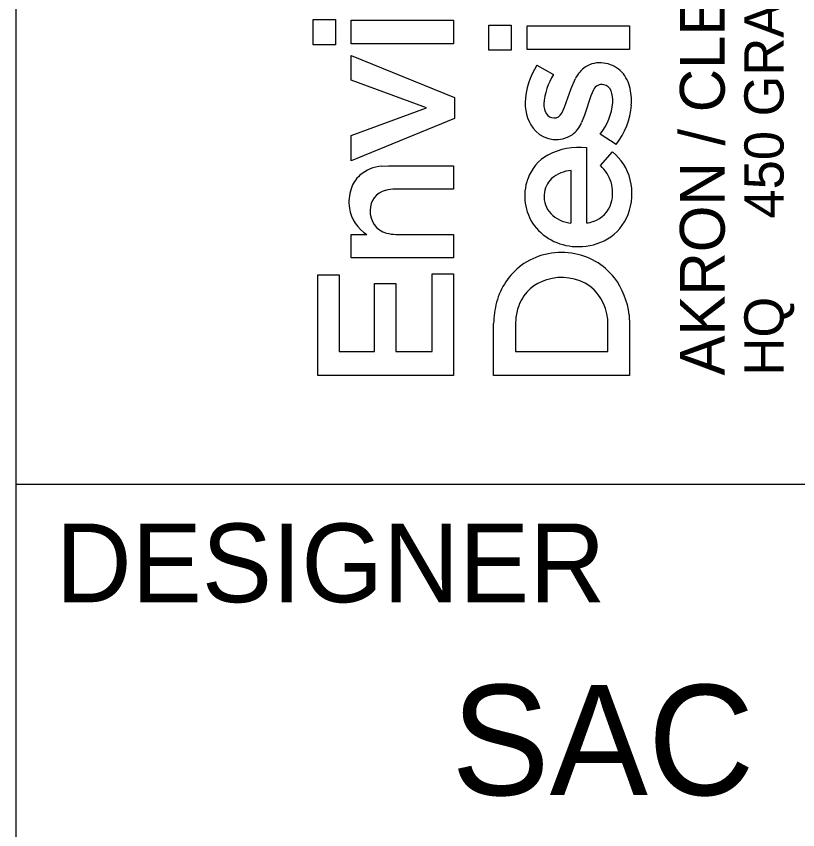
# Model space of a CAD drawing. Extents: x -0.3 to 34, y 0 to 22.
# Drawn here: x 32 to 32.993, y 2.061 to 3.094 of the extents above; entities that cross this region are included whole.
import ezdxf

# ---------------------------------------------------------------- set-up
doc = ezdxf.new("R2010")
doc.units = 0
doc.layers.add('SH_Border', color=7, linetype='Continuous')
doc.layers.add('SH_Data', color=7, linetype='Continuous')

msp = doc.modelspace()

# ---------------------------------------------------------------- linework, layer by layer
at = {"layer": 'SH_Border'}
for p, q in [((32, 0.5), (32, 21.5)), ((32, 2.5), (33.5, 2.5))]:
    msp.add_line(p, q, dxfattribs=at)
at = {"layer": 'SH_Data'}
for p, q in [((32.3771, 3.0582), (32.3771, 3.0903)), ((32.3771, 3.0903), (32.4054, 3.0903)), ((32.4054, 3.0903), (32.4054, 3.0582)), ((32.4254, 3.0594), (32.4254, 3.0893)), ((32.4254, 3.0893), (32.5557, 3.0893)), ((32.5557, 3.0893), (32.5557, 3.0594)), ((32.6005, 3.0511), (32.6005, 3.0832)), ((32.6005, 3.0832), (32.6289, 3.0832)), ((32.6289, 3.0832), (32.6289, 3.0511)), ((32.6489, 3.0523), (32.6489, 3.0822)), ((32.6489, 3.0822), (32.7792, 3.0822)), ((32.7792, 3.0822), (32.7792, 3.0523)), ((32.5557, 3.0594), (32.4254, 3.0594)), ((32.4054, 3.0582), (32.3771, 3.0582)), ((32.6289, 3.0511), (32.6005, 3.0511)), ((32.7792, 3.0523), (32.6489, 3.0523)), ((32.4254, 3.0133), (32.4254, 3.0446)), ((32.4254, 3.0446), (32.5567, 2.9913)), ((32.6615, 3.0321), (32.6827, 3.0203)), ((32.5212, 2.978), (32.4254, 3.0133)), ((32.7048, 3.0026), (32.7104, 3.0153)), ((32.6967, 2.9787), (32.7048, 3.0026)), ((32.7334, 3.001), (32.7298, 2.9933)), ((32.5567, 2.9913), (32.5567, 2.9644)), ((32.7298, 2.9933), (32.7221, 2.9688)), ((32.4254, 2.9429), (32.5212, 2.978)), ((32.693, 2.9712), (32.6967, 2.9787)), ((32.7221, 2.9688), (32.7182, 2.9592)), ((32.5567, 2.9644), (32.4254, 2.9109)), ((32.4254, 2.9109), (32.4254, 2.9429)), ((32.7621, 2.9314), (32.742, 2.9447)), ((32.7245, 2.9275), (32.7246, 2.8319)), ((32.7423, 2.9046), (32.7577, 2.922)), ((32.4644, 2.904), (32.4729, 2.9044)), ((32.4729, 2.9044), (32.5557, 2.9044)), ((32.5557, 2.9044), (32.5557, 2.8746)), ((32.7049, 2.8318), (32.7049, 2.8983)), ((32.5557, 2.8746), (32.4814, 2.8746)), ((32.7036, 2.8317), (32.7049, 2.8318)), ((32.4254, 2.7875), (32.4254, 2.8173)), ((32.4254, 2.8173), (32.4455, 2.8173)), ((32.4822, 2.8173), (32.5557, 2.8173)), ((32.5557, 2.8173), (32.5557, 2.7876)), ((32.5557, 2.7876), (32.4254, 2.7875)), ((32.383, 2.6379), (32.383, 2.766)), ((32.383, 2.766), (32.4101, 2.766)), ((32.4101, 2.766), (32.4101, 2.6683)), ((32.5286, 2.6683), (32.5286, 2.7672)), ((32.5286, 2.7672), (32.5557, 2.7672)), ((32.5557, 2.7672), (32.5557, 2.6379)), ((32.455, 2.6683), (32.455, 2.7549)), ((32.455, 2.7549), (32.4822, 2.7549)), ((32.4822, 2.7549), (32.4822, 2.6683)), ((32.6347, 2.7118), (32.6341, 2.7023)), ((32.7785, 2.715), (32.7792, 2.7021)), ((32.6064, 2.638), (32.6064, 2.704)), ((32.6341, 2.7023), (32.6341, 2.6684)), ((32.7515, 2.6683), (32.7515, 2.7024)), ((32.7792, 2.7021), (32.7792, 2.638)), ((32.4101, 2.6683), (32.455, 2.6683)), ((32.4822, 2.6683), (32.5286, 2.6683)), ((32.6341, 2.6684), (32.7515, 2.6683)), ((32.5557, 2.6379), (32.383, 2.6379)), ((32.7792, 2.638), (32.6064, 2.638))]:
    msp.add_line(p, q, dxfattribs=at)
for points in [[(32.3771, 3.0582), (32.3771, 3.0903), (32.4054, 3.0903), (32.4054, 3.0582)], [(32.4254, 3.0594), (32.4254, 3.0893), (32.5557, 3.0893), (32.5557, 3.0594)], [(32.6005, 3.0511), (32.6005, 3.0832), (32.6289, 3.0832), (32.6289, 3.0511)], [(32.6489, 3.0523), (32.6489, 3.0822), (32.7792, 3.0822), (32.7792, 3.0523)], [(32.4254, 2.9109), (32.4254, 2.9429), (32.5212, 2.978), (32.4254, 3.0133), (32.4254, 3.0446), (32.5567, 2.9913), (32.5567, 2.9644)], [(32.383, 2.6379), (32.383, 2.766), (32.4101, 2.766), (32.4101, 2.6683), (32.455, 2.6683), (32.455, 2.7549), (32.4822, 2.7549), (32.4822, 2.6683), (32.5286, 2.6683), (32.5286, 2.7672), (32.5557, 2.7672), (32.5557, 2.6379)]]:
    msp.add_lwpolyline(points, close=True, dxfattribs=at)
for points in [[(32.6615, 3.0321), (32.6827, 3.0203)], [(32.693, 2.9712), (32.6967, 2.9787), (32.7048, 3.0026), (32.7104, 3.0153)], [(32.7334, 3.001), (32.7298, 2.9933), (32.7221, 2.9688), (32.7182, 2.9592)], [(32.7621, 2.9314), (32.742, 2.9447)], [(32.7245, 2.9275), (32.7246, 2.8319)], [(32.7423, 2.9046), (32.7577, 2.922)], [(32.4644, 2.904), (32.4729, 2.9044), (32.5557, 2.9044), (32.5557, 2.8746), (32.4814, 2.8746)], [(32.7036, 2.8317), (32.7049, 2.8318), (32.7049, 2.8983)], [(32.4254, 2.7875), (32.4254, 2.8173), (32.4455, 2.8173)], [(32.4822, 2.8173), (32.5557, 2.8173), (32.5557, 2.7876), (32.4254, 2.7875)], [(32.7785, 2.715), (32.7792, 2.7021), (32.7792, 2.638), (32.6064, 2.638)], [(32.6347, 2.7118), (32.6341, 2.7023), (32.6341, 2.6684), (32.7515, 2.6683), (32.7515, 2.7024)], [(32.6064, 2.638), (32.6064, 2.704)]]:
    msp.add_lwpolyline(points, dxfattribs=at)
for centre, radius, start, end in [((32.7364, 2.9826), 0.0897, 146.531, 178.7571), ((32.7364, 2.9826), 0.0897, 146.531, 178.7571), ((32.7466, 2.9971), 0.0405, 125.5118, 153.4159), ((32.7466, 2.9971), 0.0405, 125.5118, 153.4159), ((32.7406, 3.0026), 0.0326, 80.1719, 122.5197), ((32.7406, 3.0026), 0.0326, 80.1719, 122.5197), ((32.7428, 2.9982), 0.0367, 47.7934, 84.6892), ((32.7428, 2.9982), 0.0367, 47.7934, 84.6892), ((32.7452, 2.9789), 0.0749, 146.5112, 176.9101), ((32.7452, 2.9789), 0.0749, 146.5112, 176.9101), ((32.7379, 2.9946), 0.0427, 14.9966, 46.2063), ((32.7379, 2.9946), 0.0427, 14.9966, 46.2063), ((32.7438, 2.9963), 0.0114, 76.6609, 155.7053), ((32.7438, 2.9963), 0.0114, 76.6609, 155.7053), ((32.744, 2.9951), 0.0126, 21.5098, 78.5262), ((32.744, 2.9951), 0.0126, 21.5098, 78.5262), ((32.7259, 2.9877), 0.0321, 354.5726, 22.068), ((32.7259, 2.9877), 0.0321, 354.5726, 22.068), ((32.7104, 2.9867), 0.0712, 355.8306, 15.3914), ((32.7104, 2.9867), 0.0712, 355.8306, 15.3914), ((32.6967, 2.9824), 0.0501, 177.5366, 222.7932), ((32.6967, 2.9824), 0.0501, 177.5366, 222.7932), ((32.6931, 2.9823), 0.0228, 178.4747, 211.0868), ((32.6931, 2.9823), 0.0228, 178.4747, 211.0868), ((32.6825, 2.9915), 0.0757, 321.811, 354.7969), ((32.6825, 2.9915), 0.0757, 321.811, 354.7969), ((32.6895, 2.9882), 0.0922, 321.9777, 355.8738), ((32.6895, 2.9882), 0.0922, 321.9777, 355.8738), ((32.6833, 2.9767), 0.0115, 212.2368, 268.3777), ((32.6833, 2.9767), 0.0115, 212.2368, 268.3777), ((32.6834, 2.9759), 0.0107, 267.716, 333.7337), ((32.6834, 2.9759), 0.0107, 267.716, 333.7337), ((32.681, 2.9758), 0.0408, 308.0877, 335.9874), ((32.681, 2.9758), 0.0408, 308.0877, 335.9874), ((32.686, 2.9753), 0.0375, 225.9854, 302.4797), ((32.686, 2.9753), 0.0375, 225.9854, 302.4797), ((32.7152, 2.8441), 0.0838, 83.615, 118.2876), ((32.7152, 2.8441), 0.0838, 83.615, 118.2876), ((32.7024, 2.8691), 0.0558, 118.8308, 160.6244), ((32.7024, 2.8691), 0.0558, 118.8308, 160.6244), ((32.7174, 2.8717), 0.0644, 13.5336, 51.3615), ((32.7174, 2.8717), 0.0644, 13.5336, 51.3615), ((32.4687, 2.8543), 0.0499, 94.9696, 130.2225), ((32.4687, 2.8543), 0.0499, 94.9696, 130.2225), ((32.7038, 2.8656), 0.0549, 19.0357, 45.4406), ((32.7038, 2.8656), 0.0549, 19.0357, 45.4406), ((32.7079, 2.8561), 0.0424, 94.008, 130.8817), ((32.7079, 2.8561), 0.0424, 94.008, 130.8817), ((32.4635, 2.8626), 0.0402, 132.2219, 161.6818), ((32.4635, 2.8626), 0.0402, 132.2219, 161.6818), ((32.7104, 2.8661), 0.0644, 160.5201, 215.7831), ((32.7104, 2.8661), 0.0644, 160.5201, 215.7831), ((32.7005, 2.8663), 0.0298, 132.9851, 177.179), ((32.7005, 2.8663), 0.0298, 132.9851, 177.179), ((32.7107, 2.8697), 0.047, 344.6059, 17.007), ((32.7107, 2.8697), 0.047, 344.6059, 17.007), ((32.7064, 2.8692), 0.0758, 339.3542, 13.3785), ((32.7064, 2.8692), 0.0758, 339.3542, 13.3785), ((32.4787, 2.8582), 0.056, 162.2736, 187.7919), ((32.4787, 2.8582), 0.056, 162.2736, 187.7919), ((32.4748, 2.8487), 0.025, 103.6865, 182.2187), ((32.4748, 2.8487), 0.025, 103.6865, 182.2187), ((32.4811, 2.8286), 0.046, 89.6049, 105.3284), ((32.4811, 2.8286), 0.046, 89.6049, 105.3284), ((32.7017, 2.865), 0.0311, 175.0013, 223.283), ((32.7017, 2.865), 0.0311, 175.0013, 223.283), ((32.7224, 2.8671), 0.035, 288.0077, 343.5508), ((32.7224, 2.8671), 0.035, 288.0077, 343.5508), ((32.4703, 2.858), 0.0476, 188.962, 238.7037), ((32.4703, 2.858), 0.0476, 188.962, 238.7037), ((32.4773, 2.8456), 0.0276, 175.5854, 255.1439), ((32.4773, 2.8456), 0.0276, 175.5854, 255.1439), ((32.7089, 2.8736), 0.0423, 225.0619, 262.7974), ((32.7089, 2.8736), 0.0423, 225.0619, 262.7974), ((32.7189, 2.8652), 0.0626, 300.9427, 338.7323), ((32.7189, 2.8652), 0.0626, 300.9427, 338.7323), ((32.7247, 2.8522), 0.0202, 269.7003, 294.8711), ((32.7247, 2.8522), 0.0202, 269.7003, 294.8711), ((32.7125, 2.8705), 0.0687, 217.7452, 271.6543), ((32.7125, 2.8705), 0.0687, 217.7452, 271.6543), ((32.4818, 2.8595), 0.0422, 254.0916, 270.5284), ((32.4818, 2.8595), 0.0422, 254.0916, 270.5284), ((32.7155, 2.8724), 0.0706, 269.2048, 300.3341), ((32.7155, 2.8724), 0.0706, 269.2048, 300.3341), ((32.6923, 2.7079), 0.0864, 81.194, 125.9984), ((32.6923, 2.7079), 0.0864, 81.194, 125.9984), ((32.6946, 2.7113), 0.0827, 37.8521, 82.402), ((32.6946, 2.7113), 0.0827, 37.8521, 82.402), ((32.6939, 2.7089), 0.0865, 127.2362, 165.148), ((32.6939, 2.7089), 0.0865, 127.2362, 165.148), ((32.6889, 2.7078), 0.054, 106.1881, 157.3861), ((32.6889, 2.7078), 0.054, 106.1881, 157.3861), ((32.6928, 2.6986), 0.0639, 55.6727, 107.2093), ((32.6928, 2.6986), 0.0639, 55.6727, 107.2093), ((32.6859, 2.7057), 0.0931, 5.7333, 37.304), ((32.6859, 2.7057), 0.0931, 5.7333, 37.304), ((32.6929, 2.705), 0.0587, 357.4662, 52.2665), ((32.6929, 2.705), 0.0587, 357.4662, 52.2665), ((32.7143, 2.7028), 0.1078, 164.7861, 179.3704), ((32.7143, 2.7028), 0.1078, 164.7861, 179.3704), ((32.6983, 2.7039), 0.0641, 157.3571, 172.9275), ((32.6983, 2.7039), 0.0641, 157.3571, 172.9275)]:
    msp.add_arc(centre, radius, start, end, dxfattribs=at)

# ---------------------------------------------------------------- texts
for s, height, p in [('450 GRANT ST., AKRON, OH  44311', 0.049846, (32.9749, 2.8374)), ('AKRON / CLEVELAND / COLUMBUS', 0.056969, (32.9001, 2.638)), ('HQ ', 0.04985, (32.9749, 2.638))]:
    msp.add_text(s, height=height, rotation=90, dxfattribs=at).set_placement(p)
for s, height, p in [('DESIGNER', 0.1, (32.05, 2.35)), ('SAC', 0.14, (32.5528, 2.105))]:
    msp.add_text(s, height=height, dxfattribs=at).set_placement(p)

doc.saveas('drawing.dxf')
